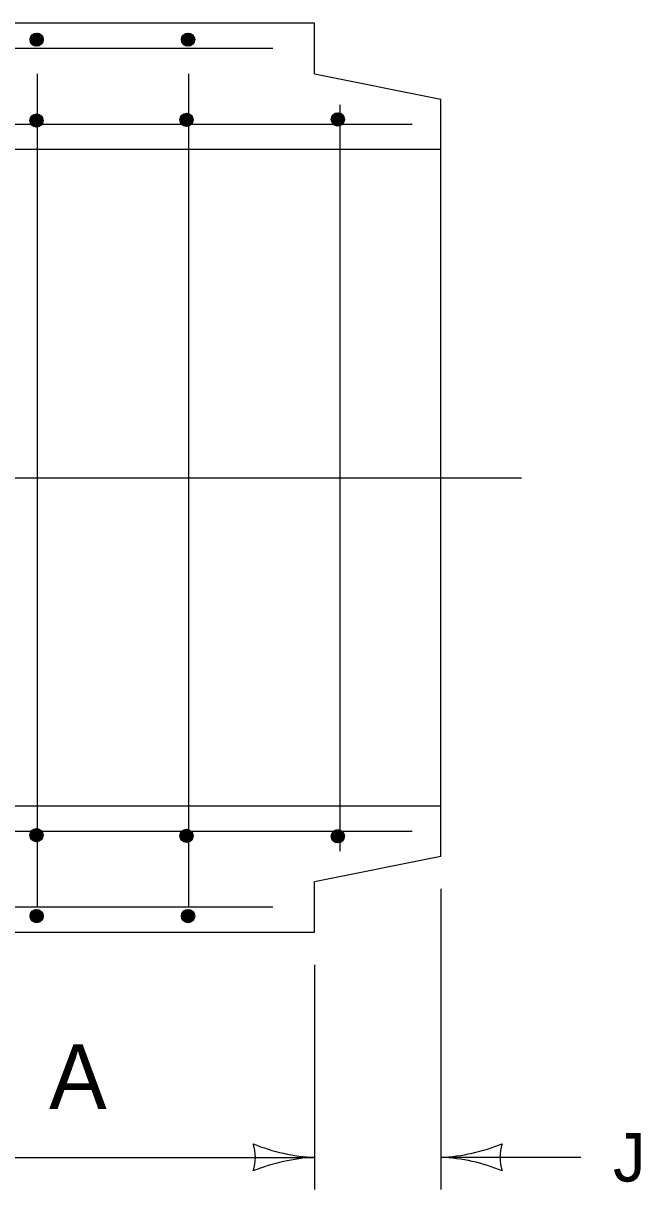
# Model space of a CAD drawing. Extents: x 49991.4 to 50021, y 49987.6 to 50011.4.
# Drawn here: x 50011.665 to 50012.43, y 49996.216 to 49997.66 of the extents above; entities that cross this region are included whole.
import ezdxf

# ---------------------------------------------------------------- set-up
doc = ezdxf.new("R2010")
doc.units = 0
for name, color, linetype in [('Level 1', 7, 'Continuous'), ('Level 2', 7, 'Continuous'), ('Level 3', 7, 'Continuous'), ('Level 5', 7, 'Continuous')]:
    doc.layers.add(name, color=color, linetype=linetype)

msp = doc.modelspace()

# ---------------------------------------------------------------- linework, layer by layer
at = {"layer": 'Level 1'}
for p, q in [((50012.0261, 49997.6602), (50009.1807, 49997.6602)), ((50012.0261, 49997.5976), (50012.0261, 49997.6602)), ((50011.9745, 49997.629), (50009.2433, 49997.629)), ((50011.6822, 49997.5976), (50011.6822, 49996.5658)), ((50011.8698, 49997.5976), (50011.8698, 49996.5658)), ((50012.0261, 49997.5976), (50012.1825, 49997.5663)), ((50012.1825, 49996.6283), (50012.1825, 49997.5663)), ((50012.0574, 49997.5594), (50012.0574, 49996.6352)), ((50012.1468, 49997.5351), (50009.3683, 49997.5351)), ((50012.1825, 49997.5038), (50009.337, 49997.5038)), ((50012.1825, 49996.6909), (50009.337, 49996.6909)), ((50012.1468, 49996.6596), (50009.3683, 49996.6596)), ((50012.1825, 49996.6283), (50012.0261, 49996.597)), ((50012.0261, 49996.5345), (50012.0261, 49996.597)), ((50011.9745, 49996.5658), (50009.2433, 49996.5658)), ((50012.0261, 49996.5345), (50009.1807, 49996.5345))]:
    msp.add_line(p, q, dxfattribs=at)
for points in [[(50011.6735, 49997.6407), (50011.6823, 49997.6318)], [(50011.6736, 49997.6394), (50011.681, 49997.6318)], [(50011.6738, 49997.6419), (50011.6835, 49997.6321)], [(50011.6738, 49997.6378), (50011.6794, 49997.6322)], [(50011.674, 49997.6429), (50011.6846, 49997.6324)], [(50011.6745, 49997.6438), (50011.6854, 49997.6327)], [(50011.675, 49997.6446), (50011.6863, 49997.6333)], [(50011.6754, 49997.6454), (50011.6755, 49997.6454), (50011.687, 49997.6338), (50011.6871, 49997.6338)], [(50011.6762, 49997.6461), (50011.6762, 49997.6461), (50011.6878, 49997.6345), (50011.6878, 49997.6345)], [(50011.6769, 49997.6466), (50011.6883, 49997.6353)], [(50011.6778, 49997.6472), (50011.6889, 49997.6361)], [(50011.6786, 49997.6476), (50011.6893, 49997.637)], [(50011.6796, 49997.6479), (50011.6896, 49997.6379)], [(50011.6807, 49997.6482), (50011.6898, 49997.639)], [(50011.682, 49997.6482), (50011.6898, 49997.6403)], [(50011.6835, 49997.648), (50011.6897, 49997.6419)], [(50011.6857, 49997.6472), (50011.6889, 49997.644)], [(50011.8611, 49997.6407), (50011.8699, 49997.6318)], [(50011.8612, 49997.6394), (50011.8686, 49997.6318)], [(50011.8614, 49997.6419), (50011.8711, 49997.6321)], [(50011.8614, 49997.6378), (50011.867, 49997.6322)], [(50011.8617, 49997.6429), (50011.8722, 49997.6324)], [(50011.8621, 49997.6438), (50011.8731, 49997.6327)], [(50011.8626, 49997.6446), (50011.8739, 49997.6333)], [(50011.863, 49997.6454), (50011.8631, 49997.6454), (50011.8746, 49997.6338), (50011.8747, 49997.6338)], [(50011.8638, 49997.6461), (50011.8638, 49997.6461), (50011.8754, 49997.6345), (50011.8754, 49997.6345)], [(50011.8645, 49997.6466), (50011.8759, 49997.6353)], [(50011.8654, 49997.6472), (50011.8765, 49997.6361)], [(50011.8662, 49997.6476), (50011.8769, 49997.637)], [(50011.8672, 49997.6479), (50011.8772, 49997.6379)], [(50011.8683, 49997.6482), (50011.8774, 49997.639)], [(50011.8697, 49997.6482), (50011.8774, 49997.6403)], [(50011.8711, 49997.648), (50011.8773, 49997.6419)], [(50011.8733, 49997.6472), (50011.8765, 49997.644)], [(50011.6752, 49997.635), (50011.6766, 49997.6336), (50011.6768, 49997.6335)], [(50011.8628, 49997.635), (50011.8642, 49997.6336), (50011.8644, 49997.6335)], [(50011.6733, 49997.5405), (50011.6821, 49997.5316)], [(50011.6734, 49997.5416), (50011.6833, 49997.5318)], [(50011.6734, 49997.5391), (50011.6808, 49997.5316)], [(50011.6736, 49997.5375), (50011.6792, 49997.5319)], [(50011.6738, 49997.5426), (50011.6843, 49997.5322)], [(50011.6742, 49997.5436), (50011.6852, 49997.5325)], [(50011.6747, 49997.5444), (50011.686, 49997.533)], [(50011.6752, 49997.5452), (50011.6753, 49997.5451), (50011.6868, 49997.5336), (50011.6869, 49997.5336)], [(50011.6759, 49997.5458), (50011.6759, 49997.5458), (50011.6874, 49997.5342), (50011.6874, 49997.5342)], [(50011.6766, 49997.5464), (50011.6881, 49997.535)], [(50011.6774, 49997.547), (50011.6886, 49997.5358)], [(50011.6783, 49997.5474), (50011.689, 49997.5367)], [(50011.6794, 49997.5477), (50011.6894, 49997.5377)], [(50011.6805, 49997.5479), (50011.6895, 49997.5388)], [(50011.6818, 49997.5479), (50011.6896, 49997.5401)], [(50011.6833, 49997.5478), (50011.6894, 49997.5416)], [(50011.6854, 49997.547), (50011.6886, 49997.5438)], [(50011.8593, 49997.5414), (50011.8681, 49997.5326)], [(50011.8594, 49997.5426), (50011.8693, 49997.5327)], [(50011.8594, 49997.5401), (50011.8668, 49997.5326)], [(50011.8596, 49997.5385), (50011.8651, 49997.5329)], [(50011.8598, 49997.5436), (50011.8702, 49997.533)], [(50011.8602, 49997.5445), (50011.8712, 49997.5334)], [(50011.8607, 49997.5454), (50011.872, 49997.5339)], [(50011.861, 49997.5358), (50011.8624, 49997.5342), (50011.8625, 49997.5342)], [(50011.8612, 49997.5462), (50011.8613, 49997.5461), (50011.8728, 49997.5345), (50011.8728, 49997.5345)], [(50011.8619, 49997.5468), (50011.8619, 49997.5468), (50011.8734, 49997.5352), (50011.8734, 49997.5352)], [(50011.8626, 49997.5474), (50011.874, 49997.5359)], [(50011.8634, 49997.5479), (50011.8746, 49997.5368)], [(50011.8643, 49997.5483), (50011.875, 49997.5376)], [(50011.8654, 49997.5486), (50011.8754, 49997.5386)], [(50011.8665, 49997.5489), (50011.8755, 49997.5398)], [(50011.8678, 49997.5489), (50011.8756, 49997.541)], [(50011.8693, 49997.5487), (50011.8754, 49997.5426)], [(50011.8714, 49997.5479), (50011.8746, 49997.5447)], [(50012.0467, 49997.5419), (50012.0556, 49997.533)], [(50012.0468, 49997.5406), (50012.0542, 49997.533)], [(50012.047, 49997.543), (50012.0567, 49997.5333)], [(50012.047, 49997.539), (50012.0526, 49997.5334)], [(50012.0473, 49997.5441), (50012.0578, 49997.5336)], [(50012.0477, 49997.545), (50012.0587, 49997.5339)], [(50012.0482, 49997.5458), (50012.0595, 49997.5345)], [(50012.0484, 49997.5362), (50012.0498, 49997.5347), (50012.05, 49997.5347)], [(50012.0487, 49997.5466), (50012.0487, 49997.5466), (50012.0602, 49997.535), (50012.0603, 49997.535)], [(50012.0494, 49997.5473), (50012.0494, 49997.5473), (50012.061, 49997.5357), (50012.061, 49997.5357)], [(50012.0502, 49997.5478), (50012.0615, 49997.5365)], [(50012.051, 49997.5484), (50012.0621, 49997.5373)], [(50012.0518, 49997.5488), (50012.0625, 49997.5382)], [(50012.0528, 49997.5491), (50012.0628, 49997.5391)], [(50012.0539, 49997.5494), (50012.063, 49997.5402)], [(50012.0553, 49997.5494), (50012.063, 49997.5415)], [(50012.0567, 49997.5492), (50012.0629, 49997.543)], [(50012.0589, 49997.5484), (50012.0621, 49997.5452)], [(50011.675, 49997.5348), (50011.6764, 49997.5334), (50011.6766, 49997.5333)], [(50011.6733, 49996.6542), (50011.6821, 49996.6631)], [(50011.6734, 49996.6556), (50011.6808, 49996.6631)], [(50011.6734, 49996.6531), (50011.6833, 49996.6629)], [(50011.6736, 49996.6572), (50011.6792, 49996.6628)], [(50011.6738, 49996.6521), (50011.6843, 49996.6626)], [(50011.6742, 49996.6511), (50011.6852, 49996.6622)], [(50011.6747, 49996.6503), (50011.686, 49996.6617)], [(50011.675, 49996.6599), (50011.6764, 49996.6614), (50011.6766, 49996.6614)], [(50011.6752, 49996.6495), (50011.6753, 49996.6496), (50011.6868, 49996.6611), (50011.6869, 49996.6611)], [(50011.6759, 49996.6489), (50011.6759, 49996.6489), (50011.6874, 49996.6605), (50011.6874, 49996.6605)], [(50011.6766, 49996.6483), (50011.6881, 49996.6597)], [(50011.6774, 49996.6478), (50011.6886, 49996.6589)], [(50011.6783, 49996.6474), (50011.689, 49996.658)], [(50011.6794, 49996.647), (50011.6894, 49996.657)], [(50011.6805, 49996.6468), (50011.6895, 49996.6559)], [(50011.6818, 49996.6468), (50011.6896, 49996.6546)], [(50011.8593, 49996.6534), (50011.8681, 49996.6622)], [(50011.8594, 49996.6546), (50011.8668, 49996.6622)], [(50011.8594, 49996.6522), (50011.8693, 49996.662)], [(50011.8596, 49996.6562), (50011.8651, 49996.6618)], [(50011.8598, 49996.6511), (50011.8702, 49996.6617)], [(50011.8602, 49996.6502), (50011.8712, 49996.6613)], [(50011.8607, 49996.6494), (50011.872, 49996.6608)], [(50011.861, 49996.659), (50011.8624, 49996.6605), (50011.8625, 49996.6606)], [(50011.8612, 49996.6486), (50011.8613, 49996.6486), (50011.8728, 49996.6602), (50011.8728, 49996.6602)], [(50011.8619, 49996.6479), (50011.8619, 49996.6479), (50011.8734, 49996.6595), (50011.8734, 49996.6595)], [(50011.8626, 49996.6474), (50011.874, 49996.6588)], [(50011.8634, 49996.6468), (50011.8746, 49996.6579)], [(50011.8643, 49996.6464), (50011.875, 49996.6571)], [(50011.8654, 49996.6461), (50011.8754, 49996.6561)], [(50011.8665, 49996.6458), (50011.8755, 49996.655)], [(50012.0467, 49996.6528), (50012.0556, 49996.6617)], [(50012.0468, 49996.6542), (50012.0542, 49996.6617)], [(50012.047, 49996.6558), (50012.0526, 49996.6614)], [(50012.047, 49996.6517), (50012.0567, 49996.6614)], [(50012.0473, 49996.6506), (50012.0578, 49996.6611)], [(50012.0477, 49996.6497), (50012.0587, 49996.6608)], [(50012.0482, 49996.6489), (50012.0595, 49996.6602)], [(50012.0484, 49996.6585), (50012.0498, 49996.66), (50012.05, 49996.66)], [(50012.0487, 49996.6481), (50012.0487, 49996.6482), (50012.0602, 49996.6597), (50012.0603, 49996.6597)], [(50012.0494, 49996.6474), (50012.0494, 49996.6474), (50012.061, 49996.659), (50012.061, 49996.659)], [(50012.0502, 49996.6469), (50012.0615, 49996.6582)], [(50012.051, 49996.6463), (50012.0621, 49996.6574)], [(50012.0518, 49996.6459), (50012.0625, 49996.6566)], [(50012.0528, 49996.6456), (50012.0628, 49996.6556)], [(50012.0539, 49996.6454), (50012.063, 49996.6545)], [(50011.6833, 49996.647), (50011.6894, 49996.6531)], [(50011.6854, 49996.6478), (50011.6886, 49996.651)], [(50011.8678, 49996.6458), (50011.8756, 49996.6537)], [(50011.8693, 49996.646), (50011.8754, 49996.6522)], [(50011.8714, 49996.6468), (50011.8746, 49996.65)], [(50012.0553, 49996.6454), (50012.063, 49996.6532)], [(50012.0567, 49996.6455), (50012.0629, 49996.6517)], [(50012.0589, 49996.6463), (50012.0621, 49996.6495)], [(50011.6735, 49996.554), (50011.6823, 49996.5629)], [(50011.6736, 49996.5554), (50011.681, 49996.5629)], [(50011.6738, 49996.557), (50011.6794, 49996.5626)], [(50011.6738, 49996.5528), (50011.6835, 49996.5626)], [(50011.674, 49996.5518), (50011.6846, 49996.5623)], [(50011.6745, 49996.5509), (50011.6854, 49996.562)], [(50011.675, 49996.5501), (50011.6863, 49996.5614)], [(50011.6752, 49996.5597), (50011.6766, 49996.5611), (50011.6768, 49996.5612)], [(50011.6754, 49996.5493), (50011.6755, 49996.5494), (50011.687, 49996.5609), (50011.6871, 49996.5609)], [(50011.6762, 49996.5486), (50011.6762, 49996.5486), (50011.6878, 49996.5602), (50011.6878, 49996.5602)], [(50011.6769, 49996.5481), (50011.6883, 49996.5594)], [(50011.6778, 49996.5475), (50011.6889, 49996.5586)], [(50011.6786, 49996.5471), (50011.6893, 49996.5578)], [(50011.6796, 49996.5468), (50011.6896, 49996.5568)], [(50011.6807, 49996.5466), (50011.6898, 49996.5557)], [(50011.682, 49996.5466), (50011.6898, 49996.5544)], [(50011.8611, 49996.554), (50011.8699, 49996.5629)], [(50011.8612, 49996.5554), (50011.8686, 49996.5629)], [(50011.8614, 49996.557), (50011.867, 49996.5626)], [(50011.8614, 49996.5528), (50011.8711, 49996.5626)], [(50011.8617, 49996.5518), (50011.8722, 49996.5623)], [(50011.8621, 49996.5509), (50011.8731, 49996.562)], [(50011.8626, 49996.5501), (50011.8739, 49996.5614)], [(50011.8628, 49996.5597), (50011.8642, 49996.5611), (50011.8644, 49996.5612)], [(50011.863, 49996.5493), (50011.8631, 49996.5494), (50011.8746, 49996.5609), (50011.8747, 49996.5609)], [(50011.8638, 49996.5486), (50011.8638, 49996.5486), (50011.8754, 49996.5602), (50011.8754, 49996.5602)], [(50011.8645, 49996.5481), (50011.8759, 49996.5594)], [(50011.8654, 49996.5475), (50011.8765, 49996.5586)], [(50011.8662, 49996.5471), (50011.8769, 49996.5578)], [(50011.8672, 49996.5468), (50011.8772, 49996.5568)], [(50011.8683, 49996.5466), (50011.8774, 49996.5557)], [(50011.8697, 49996.5466), (50011.8774, 49996.5544)], [(50011.6835, 49996.5467), (50011.6897, 49996.5528)], [(50011.6857, 49996.5475), (50011.6889, 49996.5507)], [(50011.8711, 49996.5467), (50011.8773, 49996.5528)], [(50011.8733, 49996.5475), (50011.8765, 49996.5507)]]:
    msp.add_lwpolyline(points, dxfattribs=at)
for centre in [(50011.6817, 49997.64), (50011.8693, 49997.64), (50011.6815, 49997.5398), (50011.8674, 49997.5407), (50012.0549, 49997.5412), (50011.6815, 49996.6549), (50011.8674, 49996.654), (50012.0549, 49996.6535), (50011.6817, 49996.5547), (50011.8693, 49996.5547)]:
    msp.add_circle(centre, 0.00819, dxfattribs=at)
at = {"layer": 'Level 3'}
for p, q in [((50012.1825, 49996.5883), (50012.1825, 49996.2159)), ((50012.0261, 49996.4945), (50012.0261, 49996.2159)), ((50009.1807, 49996.2559), (50012.0261, 49996.2559)), ((50012.3559, 49996.2559), (50012.1825, 49996.2559))]:
    msp.add_line(p, q, dxfattribs=at)
for centre, radius, start, end in [((50012.0353, 49996.478), 0.2223, 247.456, 267.6395), ((50011.8979, 49996.2559), 0.0548, 342.1388, 17.8612), ((50012.171, 49996.4886), 0.233, 272.8273, 292.0772), ((50012.3107, 49996.2559), 0.0548, 162.1388, 197.8612), ((50012.0376, 49996.0232), 0.233, 92.8273, 112.0772), ((50012.1734, 49996.0338), 0.2223, 67.456, 87.6395)]:
    msp.add_arc(centre, radius, start, end, dxfattribs=at)
at = {"layer": 'Level 5'}
msp.add_line((50009.0807, 49997.0973), (50012.2825, 49997.0973), dxfattribs=at)

# ---------------------------------------------------------------- texts
at = {"layer": 'Level 2'}
for s, height, p in [('A', 0.08, (50011.6971, 49996.3159)), ('J', 0.06, (50012.3959, 49996.2259))]:
    msp.add_text(s, height=height, dxfattribs=at).set_placement(p)

doc.saveas('drawing.dxf')
